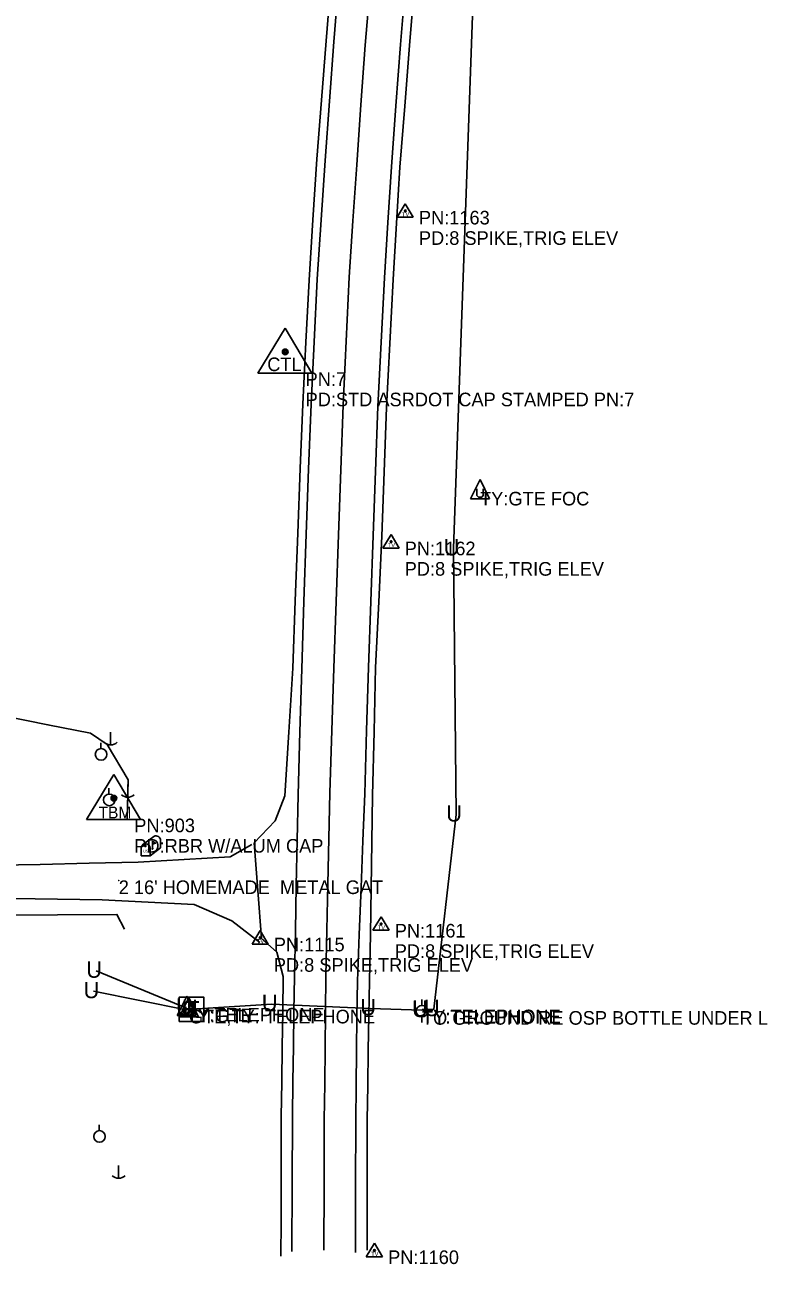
# Model space of a CAD drawing. Extents: x 1445297 to 1476720, y 2042269 to 2057889.
# Drawn here: x 1445578.3 to 1445851, y 2053293.7 to 2053749 of the extents above; entities that cross this region are included whole.
import ezdxf

# ---------------------------------------------------------------- set-up
doc = ezdxf.new("R2010")
doc.units = 0
for name, color, linetype in [('S_DITCHLINE', 7, 'Continuous'), ('S_DRIVEWAY', 7, 'Continuous'), ('S_EDGE_PAVEMENT', 7, 'Continuous'), ('S_GATE_ANNOT', 7, 'Continuous'), ('S_MAILBOX', 7, 'Continuous'), ('S_MSC_PT_SYM', 7, 'Continuous'), ('S_PAVEMENT_CROWN', 7, 'Continuous'), ('S_PRIMARY_CTL', 7, 'Continuous'), ('S_PRIMARY_CTL_ANNOT', 7, 'Continuous'), ('S_SECONDARY_CTL', 7, 'Continuous'), ('S_SECONDARY_CTL_ANNOT', 7, 'Continuous'), ('S_SHOULDER', 7, 'Continuous'), ('S_TELEPHONE_UTILITIES', 7, 'Continuous'), ('S_TELEPHONE_UTILITIES_ANNOT', 7, 'Continuous'), ('S_UNDERGROUND_CABLE', 7, 'Continuous'), ('S_UNDERGROUND_CABLE_ANNOT', 7, 'Continuous'), ('S_UTILITY_POLE', 7, 'Continuous'), ('S_UTILITY_POLE_ANNOT', 7, 'Continuous'), ('S_UTL_PT_SYM', 7, 'Continuous')]:
    doc.layers.add(name, color=color, linetype=linetype)

msp = doc.modelspace()

# ---------------------------------------------------------------- linework, layer by layer
at = {"layer": 'S_DITCHLINE'}
for points in [[(1445615.87, 2053456.8), (1445616.26, 2053471.68), (1445608.56, 2053484.64), (1445602.41, 2053488.81), (1445586.73, 2053491.91), (1445571.06, 2053495), (1445547.47, 2053499.13), (1445523.88, 2053503.25), (1445502.22, 2053509.65), (1445480.56, 2053516.06), (1445464.18, 2053519.41), (1445447.8, 2053522.76), (1445431.41, 2053526.11), (1445415.03, 2053529.45), (1445401.39, 2053532.26), (1445387.74, 2053535.07), (1445374.09, 2053537.87), (1445360.44, 2053540.68), (1445336.65, 2053542.96), (1445312.85, 2053545.24)], [(1445614.92, 2053416.79), (1445612.09, 2053422.21), (1445590.3, 2053422.05), (1445568.5, 2053421.9), (1445555.99, 2053421.71), (1445543.49, 2053421.52)]]:
    msp.add_lwpolyline(points, dxfattribs=at)
at = {"layer": 'S_DRIVEWAY'}
for points in [[(1445661.61, 2053447.87), (1445653.76, 2053443.33), (1445636.84, 2053442.4), (1445619.91, 2053441.46), (1445601.9, 2053441.02), (1445583.88, 2053440.57), (1445559.97, 2053440.13), (1445536.07, 2053439.69), (1445512.74, 2053437.08), (1445489.41, 2053434.47), (1445466.04, 2053432.05), (1445442.66, 2053429.63), (1445429.9, 2053429.37), (1445417.14, 2053429.11), (1445404.39, 2053428.85), (1445391.63, 2053428.58), (1445378.91, 2053428.91), (1445366.2, 2053429.24), (1445353.49, 2053429.56), (1445340.77, 2053429.89), (1445318.85, 2053429.7), (1445296.93, 2053429.52)], [(1445398.2, 2053374.01), (1445415.04, 2053375.6), (1445431.88, 2053377.2), (1445448.05, 2053377.97), (1445464.22, 2053378.74), (1445462.13, 2053397.98), (1445460.04, 2053417.23), (1445472.5, 2053419.07), (1445484.95, 2053420.91), (1445497.4, 2053422.75), (1445509.86, 2053424.59), (1445533.64, 2053426.48), (1445557.42, 2053428.37), (1445582.02, 2053427.95), (1445606.63, 2053427.54), (1445623.57, 2053426.72), (1445640.51, 2053425.89), (1445654.34, 2053419.81), (1445664.64, 2053411.89)]]:
    msp.add_lwpolyline(points, dxfattribs=at)
at = {"layer": 'S_EDGE_PAVEMENT'}
for points in [[(1445676.32, 2053298.41), (1445676.44, 2053323.17), (1445676.57, 2053347.92), (1445676.75, 2053360.79), (1445676.94, 2053373.65), (1445677.13, 2053386.51), (1445677.31, 2053399.38), (1445677.65, 2053416.08), (1445677.98, 2053432.79), (1445678.31, 2053449.49), (1445678.65, 2053466.19), (1445679.31, 2053489.34), (1445679.98, 2053512.49), (1445680.78, 2053537.19), (1445681.57, 2053561.9), (1445682.49, 2053585.76), (1445683.4, 2053609.62), (1445684.56, 2053632.62), (1445685.72, 2053655.63), (1445687.15, 2053677.38), (1445688.58, 2053699.14), (1445690.17, 2053720.98), (1445691.76, 2053742.83), (1445693.79, 2053767.11)], [(1445699.78, 2053298), (1445699.8, 2053322.25), (1445699.82, 2053346.49), (1445699.98, 2053359.28), (1445700.14, 2053372.07), (1445700.29, 2053384.87), (1445700.45, 2053397.66), (1445701.13, 2053414.87), (1445701.8, 2053432.08), (1445702.47, 2053449.29), (1445703.14, 2053466.51), (1445703.82, 2053489.73), (1445704.51, 2053512.96), (1445705.38, 2053537.17), (1445706.26, 2053561.38), (1445707.1, 2053585.09), (1445707.94, 2053608.8), (1445709.16, 2053632.43), (1445710.38, 2053656.06), (1445711.66, 2053676.46), (1445712.94, 2053696.85), (1445714.61, 2053719.31), (1445716.28, 2053741.76), (1445718.26, 2053765.38)]]:
    msp.add_lwpolyline(points, dxfattribs=at)
at = {"layer": 'S_MAILBOX'}
for p, q in [((1445621.55, 2053447.79), (1445625.69, 2053450.9)), ((1445625.17, 2053449.08), (1445625.17, 2053446.37)), ((1445628.12, 2053449.43), (1445628.12, 2053446.71)), ((1445621, 2053446.52), (1445621, 2053443.8)), ((1445624.32, 2053443.8), (1445628.12, 2053446.71)), ((1445624.32, 2053446.52), (1445624.32, 2053443.8)), ((1445621, 2053443.8), (1445624.32, 2053443.8))]:
    msp.add_line(p, q, dxfattribs=at)
for points in [[(1445625.17, 2053449.08), (1445626.28, 2053448.42), (1445625.17, 2053448.07)], [(1445622.18, 2053447.63), (1445622.4, 2053447.5), (1445622.4, 2053447.11), (1445622.71, 2053447.11), (1445622.71, 2053447.47), (1445622.52, 2053447.72), (1445622.18, 2053447.66)]]:
    msp.add_lwpolyline(points, dxfattribs=at)
for centre, end in [((1445626.46, 2053449.43), 117.5718), ((1445622.66, 2053446.52), 180)]:
    msp.add_arc(centre, 1.66, 0, end, dxfattribs=at)
msp.add_ellipse((1445625.17, 2053446.37), major_axis=(0.145, 0.132), ratio=0.564646, dxfattribs=at)
at = {"layer": 'S_MSC_PT_SYM'}
msp.add_lwpolyline([(1445612.77, 2053434.7), (1445612.77, 2053434.75), (1445612.77, 2053434.7), (1445612.72, 2053434.7), (1445612.77, 2053434.7), (1445612.77, 2053434.65), (1445612.77, 2053434.7), (1445612.82, 2053434.7)], dxfattribs=at)
at = {"layer": 'S_PAVEMENT_CROWN'}
msp.add_lwpolyline([(1445688.09, 2053298.82), (1445688.18, 2053322.81), (1445688.27, 2053346.81), (1445688.43, 2053360.01), (1445688.58, 2053373.22), (1445688.74, 2053386.43), (1445688.89, 2053399.64), (1445689.25, 2053416.46), (1445689.61, 2053433.27), (1445689.97, 2053450.09), (1445690.34, 2053466.91), (1445691.06, 2053489.77), (1445691.77, 2053512.64), (1445692.66, 2053537.15), (1445693.54, 2053561.67), (1445694.4, 2053585.49), (1445695.25, 2053609.31), (1445696.36, 2053632.79), (1445697.46, 2053656.27), (1445698.82, 2053676.96), (1445700.18, 2053697.65), (1445701.76, 2053719.6), (1445703.34, 2053741.56), (1445705.43, 2053765.89)], dxfattribs=at)
at = {"layer": 'S_PRIMARY_CTL'}
for p, q in [((1445673.92, 2053637.59), (1445663.89, 2053621.08)), ((1445673.92, 2053637.59), (1445683.75, 2053621.08)), ((1445663.89, 2053621.08), (1445683.75, 2053621.08)), ((1445610.98, 2053473.61), (1445600.95, 2053457.1)), ((1445610.98, 2053473.61), (1445620.81, 2053457.1)), ((1445600.95, 2053457.1), (1445620.81, 2053457.1))]:
    msp.add_line(p, q, dxfattribs=at)
for centre, radius in [((1445673.92, 2053628.89), 1.04), ((1445673.92, 2053628.89), 0.609), ((1445673.92, 2053628.89), 0.344), ((1445610.98, 2053464.91), 1.04), ((1445610.98, 2053464.91), 0.609), ((1445610.98, 2053464.91), 0.344)]:
    msp.add_circle(centre, radius, dxfattribs=at)
at = {"layer": 'S_SECONDARY_CTL'}
for p, q in [((1445718.04, 2053683.3), (1445715.03, 2053678.34)), ((1445718.04, 2053683.3), (1445720.99, 2053678.34)), ((1445715.03, 2053678.34), (1445720.99, 2053678.34)), ((1445712.82, 2053561.77), (1445709.81, 2053556.82)), ((1445712.82, 2053561.77), (1445715.77, 2053556.82)), ((1445709.81, 2053556.82), (1445715.77, 2053556.82)), ((1445709.16, 2053421.34), (1445706.15, 2053416.39)), ((1445709.16, 2053421.34), (1445712.11, 2053416.39)), ((1445664.74, 2053416.26), (1445661.73, 2053411.31)), ((1445664.74, 2053416.26), (1445667.69, 2053411.31)), ((1445706.15, 2053416.39), (1445712.11, 2053416.39)), ((1445661.73, 2053411.31), (1445667.69, 2053411.31)), ((1445706.73, 2053301.39), (1445703.72, 2053296.44)), ((1445706.73, 2053301.39), (1445709.68, 2053296.44)), ((1445703.72, 2053296.44), (1445709.68, 2053296.44))]:
    msp.add_line(p, q, dxfattribs=at)
for centre, radius in [((1445718.04, 2053680.69), 0.311), ((1445718.04, 2053680.69), 0.183), ((1445718.04, 2053680.69), 0.103), ((1445712.82, 2053559.16), 0.311), ((1445712.82, 2053559.16), 0.183), ((1445712.82, 2053559.16), 0.103), ((1445709.16, 2053418.73), 0.311), ((1445709.16, 2053418.73), 0.183), ((1445709.16, 2053418.73), 0.103), ((1445664.74, 2053413.65), 0.311), ((1445664.74, 2053413.65), 0.183), ((1445664.74, 2053413.65), 0.103), ((1445706.73, 2053298.78), 0.311), ((1445706.73, 2053298.78), 0.183), ((1445706.73, 2053298.78), 0.103)]:
    msp.add_circle(centre, radius, dxfattribs=at)
at = {"layer": 'S_SHOULDER'}
for points in [[(1445672.36, 2053296.65), (1445672.38, 2053309.45), (1445672.41, 2053322.26), (1445672.43, 2053335.06), (1445672.46, 2053347.86), (1445672.65, 2053360.74), (1445672.84, 2053373.62), (1445673.02, 2053386.5), (1445673.21, 2053399.38), (1445670.87, 2053408.29), (1445665.22, 2053413.42), (1445663.84, 2053430.96), (1445662.47, 2053448.49), (1445670.29, 2053456.57), (1445673.77, 2053465.82), (1445675.27, 2053489.23), (1445676.76, 2053512.64), (1445677.64, 2053537.47), (1445678.52, 2053562.29), (1445679.44, 2053585.99), (1445680.35, 2053609.69), (1445681.52, 2053632.45), (1445682.7, 2053655.21), (1445684.12, 2053677.42), (1445685.54, 2053699.62), (1445687.23, 2053721.36), (1445688.92, 2053743.09), (1445690.9, 2053767.46)], [(1445703.99, 2053298.9), (1445703.99, 2053322.76), (1445703.98, 2053346.62), (1445704.22, 2053359.43), (1445704.46, 2053372.24), (1445704.7, 2053385.04), (1445704.95, 2053397.85), (1445705.21, 2053414.88), (1445705.48, 2053431.9), (1445705.75, 2053448.93), (1445706.02, 2053465.96), (1445706.58, 2053489.42), (1445707.14, 2053512.89), (1445708.26, 2053537.04), (1445709.38, 2053561.18), (1445710.27, 2053584.79), (1445711.16, 2053608.4), (1445712.35, 2053631.96), (1445713.53, 2053655.52), (1445714.8, 2053676.14), (1445716.07, 2053696.76), (1445717.81, 2053719.09), (1445719.56, 2053741.42), (1445721.59, 2053765.14)]]:
    msp.add_lwpolyline(points, dxfattribs=at)
at = {"layer": 'S_TELEPHONE_UTILITIES'}
for p, q in [((1445724.14, 2053388.78), (1445724.14, 2053390.91)), ((1445724.14, 2053384.56), (1445724.14, 2053382.51))]:
    msp.add_line(p, q, dxfattribs=at)
msp.add_lwpolyline([(1445634.98, 2053382.87), (1445634.98, 2053391.87), (1445643.98, 2053391.87), (1445643.98, 2053382.87)], close=True, dxfattribs=at)
msp.add_circle((1445724.16, 2053386.7), 2.11, dxfattribs=at)
at = {"layer": 'S_UNDERGROUND_CABLE'}
for p, q in [((1445735.77, 2053556.65), (1445744.38, 2053798.49)), ((1445736.68, 2053458.89), (1445735.77, 2053556.65)), ((1445728.54, 2053387.39), (1445736.68, 2053458.89)), ((1445637.46, 2053387.88), (1445604.46, 2053401.49)), ((1445637.59, 2053387.19), (1445603.47, 2053393.98)), ((1445639.62, 2053387.42), (1445637.59, 2053387.19)), ((1445668.95, 2053389.3), (1445639.62, 2053387.42)), ((1445705.14, 2053387.7), (1445668.95, 2053389.3)), ((1445724.17, 2053387.06), (1445705.14, 2053387.7)), ((1445724.26, 2053387.23), (1445728.54, 2053387.39))]:
    msp.add_line(p, q, dxfattribs=at)
at = {"layer": 'S_UTILITY_POLE'}
for p, q in [((1445745.52, 2053581.99), (1445742, 2053574.9)), ((1445745.52, 2053581.99), (1445749.01, 2053574.9)), ((1445744.32, 2053576.14), (1445744.32, 2053578.58)), ((1445746.69, 2053578.58), (1445746.69, 2053576.14)), ((1445742, 2053574.9), (1445749.01, 2053574.9)), ((1445744.94, 2053575.48), (1445744.32, 2053576.14)), ((1445746.14, 2053575.48), (1445744.94, 2053575.48)), ((1445746.69, 2053576.14), (1445746.14, 2053575.48)), ((1445606.17, 2053483.17), (1445606.17, 2053485.27)), ((1445609.79, 2053489.22), (1445609.79, 2053484.5)), ((1445609.18, 2053466.43), (1445609.18, 2053468.54)), ((1445616.08, 2053469.95), (1445616.08, 2053465.22)), ((1445637.76, 2053392.14), (1445634.23, 2053385.05)), ((1445638.57, 2053391.71), (1445635.05, 2053384.62)), ((1445637.76, 2053392.14), (1445641.25, 2053385.05)), ((1445638.57, 2053391.71), (1445642.06, 2053384.62)), ((1445636.56, 2053386.29), (1445636.56, 2053388.73)), ((1445637.18, 2053385.63), (1445636.56, 2053386.29)), ((1445638.38, 2053385.63), (1445637.18, 2053385.63)), ((1445637.37, 2053385.86), (1445637.37, 2053388.3)), ((1445637.99, 2053385.2), (1445637.37, 2053385.86)), ((1445639.19, 2053385.2), (1445637.99, 2053385.2)), ((1445638.92, 2053386.29), (1445638.38, 2053385.63)), ((1445638.92, 2053388.73), (1445638.92, 2053386.29)), ((1445639.74, 2053385.86), (1445639.19, 2053385.2)), ((1445639.74, 2053388.3), (1445639.74, 2053385.86)), ((1445634.23, 2053385.05), (1445641.25, 2053385.05)), ((1445635.05, 2053384.62), (1445642.06, 2053384.62)), ((1445605.58, 2053342.79), (1445605.58, 2053344.9)), ((1445612.68, 2053330.02), (1445612.68, 2053325.29))]:
    msp.add_line(p, q, dxfattribs=at)
for centre in [(1445606.29, 2053481.02), (1445609.3, 2053464.29), (1445605.71, 2053340.65)]:
    msp.add_circle(centre, 2.13, dxfattribs=at)
for centre in [(1445609.85, 2053487.92), (1445616.14, 2053468.65), (1445612.74, 2053328.71)]:
    msp.add_arc(centre, 3.41, 226.3972, 313.6028, dxfattribs=at)

# ---------------------------------------------------------------- texts
at = {"layer": 'S_GATE_ANNOT'}
msp.add_text("2 16' HOMEMADE  METAL GAT", height=5, dxfattribs=at).set_placement((1445612.77, 2053429.7))
at = {"layer": 'S_MAILBOX'}
msp.add_text('US', height=0.96, dxfattribs=at).set_placement((1445621.76, 2053445))
at = {"layer": 'S_PRIMARY_CTL'}
for s, height, p in [('CTL', 5, (1445667.33, 2053621.81)), ('TBM', 4.287, (1445605.33, 2053457.52))]:
    msp.add_text(s, height=height, dxfattribs=at).set_placement(p)
at = {"layer": 'S_PRIMARY_CTL_ANNOT'}
for s, p in [('PN:7', (1445681.42, 2053616.39)), ('PD:STD ASRDOT CAP STAMPED PN:7', (1445681.42, 2053608.89)), ('PN:903', (1445618.48, 2053452.41)), ('PD:RBR W/ALUM CAP', (1445618.48, 2053444.91))]:
    msp.add_text(s, height=5, dxfattribs=at).set_placement(p)
at = {"layer": 'S_SECONDARY_CTL'}
for p in [(1445716.84, 2053678.68), (1445711.62, 2053557.15), (1445707.96, 2053416.72), (1445663.54, 2053411.64), (1445705.53, 2053296.77)]:
    msp.add_text('TV', height=1.5, dxfattribs=at).set_placement(p)
at = {"layer": 'S_SECONDARY_CTL_ANNOT'}
for s, p in [('PN:1163', (1445723.04, 2053675.69)), ('PD:8 SPIKE,TRIG ELEV', (1445723.04, 2053668.19)), ('PN:1162', (1445717.82, 2053554.16)), ('PD:8 SPIKE,TRIG ELEV', (1445717.82, 2053546.66)), ('PN:1161', (1445714.16, 2053413.73)), ('PN:1115', (1445669.74, 2053408.65)), ('PD:8 SPIKE,TRIG ELEV', (1445714.16, 2053406.23)), ('PD:8 SPIKE,TRIG ELEV', (1445669.74, 2053401.15)), ('PN:1160', (1445711.73, 2053293.78))]:
    msp.add_text(s, height=5, dxfattribs=at).set_placement(p)
at = {"layer": 'S_TELEPHONE_UTILITIES'}
msp.add_text('T', height=6, dxfattribs=at).set_placement((1445637.55, 2053384.37))
at = {"layer": 'S_TELEPHONE_UTILITIES_ANNOT'}
msp.add_text('TO GROUND RE OSP BOTTLE UNDER L', height=5, dxfattribs=at).set_placement((1445724.16, 2053381.7))
at = {"layer": 'S_UNDERGROUND_CABLE_ANNOT'}
for p in [(1445637.46, 2053382.88), (1445724.17, 2053382.06), (1445724.26, 2053382.23)]:
    msp.add_text('TY:TELEPHONE', height=5, dxfattribs=at).set_placement(p)
at = {"layer": 'S_UTILITY_POLE_ANNOT'}
for s, p in [('TY:GTE FOC', (1445745.52, 2053572.46)), ('TY:GTE', (1445637.76, 2053382.61)), ('GTE,TY: TELEPHONE', (1445638.57, 2053382.18))]:
    msp.add_text(s, height=5, dxfattribs=at).set_placement(p)
at = {"layer": 'S_UTL_PT_SYM'}
for p in [(1445732.14, 2053554.1), (1445733.05, 2053456.34), (1445600.83, 2053398.94), (1445599.84, 2053391.44), (1445633.83, 2053385.33), (1445633.96, 2053384.64), (1445635.99, 2053384.88), (1445665.32, 2053386.75), (1445701.51, 2053385.15), (1445720.54, 2053384.52), (1445720.63, 2053384.69), (1445724.91, 2053384.84)]:
    msp.add_text('U', height=6, dxfattribs=at).set_placement(p)

doc.saveas('drawing.dxf')
